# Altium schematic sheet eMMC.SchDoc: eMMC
size A4; CompanyName: STMicroelectronics; DocumentNumber: MB1263; Revision: C-04; SheetNumber: 9; SheetTotal: 11; Project: STM32MP157-EVAL
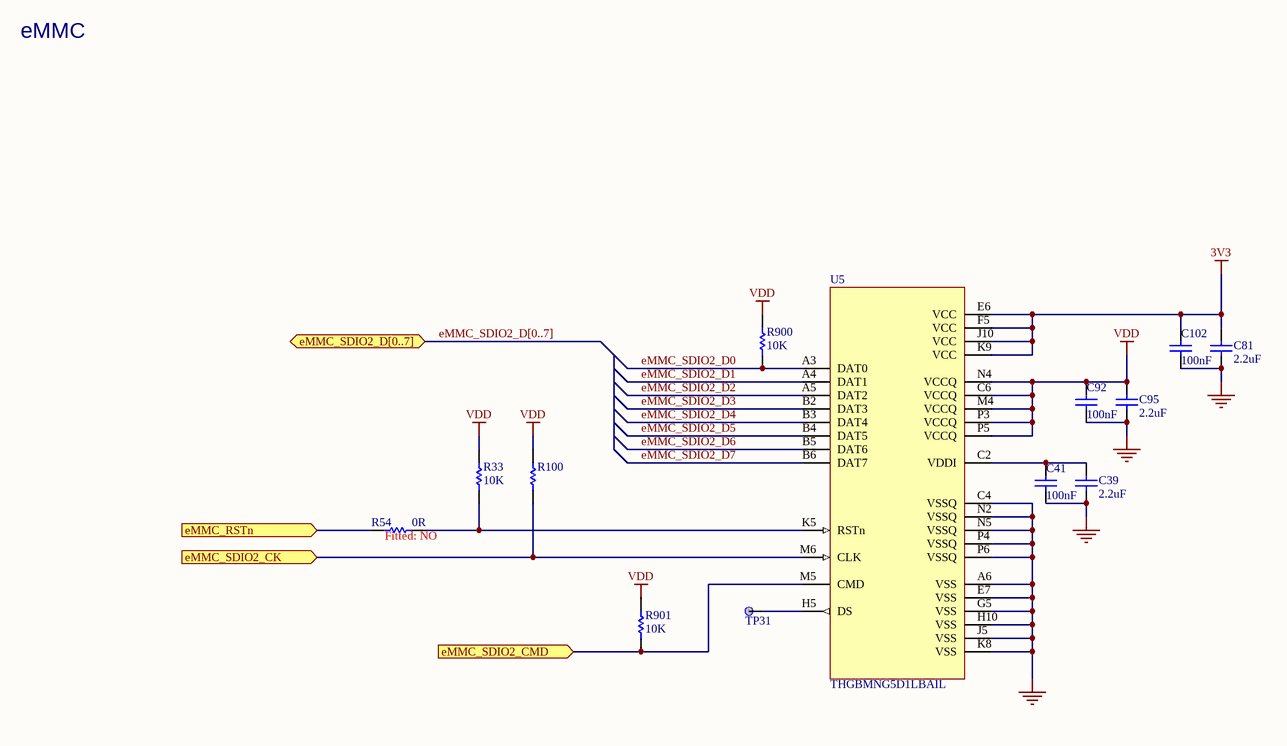
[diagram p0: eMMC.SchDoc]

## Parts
C39  2.2uF  [C0603]
C41  100nF  [C0402]
C81  2.2uF  [C0603]
C92  100nF  [C0402]
C95  2.2uF  [C0603]
C102  100nF  [C0402]
R33  10K  [R0402]
R54  0R  Fitted: NO  [R0402]
R100  10K  [R0402]  (value not drawn)
R900  10K  [R0402]
R901  10K  [R0402]
TP31  TP  [TP_SMD_1MM]  (value not drawn)  (no BOM)
U5  THGBMNG5D1LBAIL  [ICC_P-WFBGA153_13X11P5_P050]

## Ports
eMMC_RSTn (in), eMMC_SDIO2_CK (in), eMMC_SDIO2_CMD (in), eMMC_SDIO2_D[0..7] (bidir)

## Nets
3V3: C81.1 C102.2 U5.E6(VCC) U5.F5(VCC) U5.J10(VCC) U5.K9(VCC)
GND: C39.2 C41.1 C81.2 C92.1 C95.2 C102.1 U5.A6(VSS) U5.C4(VSSQ) U5.E7(VSS) U5.G5(VSS) U5.H10(VSS) U5.J5(VSS) U5.K8(VSS) U5.N2(VSSQ) U5.N5(VSSQ) U5.P4(VSSQ) U5.P6(VSSQ)
VDD: C92.2 C95.1 R33.2 R100.2 R900.2 R901.2 U5.C6(VCCQ) U5.M4(VCCQ) U5.N4(VCCQ) U5.P3(VCCQ) U5.P5(VCCQ)
eMMC_RSTn: R54.1 ; port eMMC_RSTn
eMMC_SDIO2_CK: R100.1 U5.M6(CLK) ; port eMMC_SDIO2_CK
eMMC_SDIO2_CMD: R901.1 U5.M5(CMD) ; port eMMC_SDIO2_CMD
eMMC_SDIO2_D0: R900.1 U5.A3(DAT0)
eMMC_SDIO2_D1: U5.A4(DAT1)
eMMC_SDIO2_D2: U5.A5(DAT2)
eMMC_SDIO2_D3: U5.B2(DAT3)
eMMC_SDIO2_D4: U5.B3(DAT4)
eMMC_SDIO2_D5: U5.B4(DAT5)
eMMC_SDIO2_D6: U5.B5(DAT6)
eMMC_SDIO2_D7: U5.B6(DAT7)
NetC39_1: C39.1 C41.2 U5.C2(VDDI)
NetR33_1: R33.1 R54.2 U5.K5(RSTn)
NetTP31_1: TP31.1 U5.H5(DS)

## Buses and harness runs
bus eMMC_SDIO2_D[0..7] = port eMMC_SDIO2_D[0..7]

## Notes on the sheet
- eMMC

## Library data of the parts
C39 C81 C95 = Cap_2.2uF_X5R_10%_0603: Capacitor,2.2uF,10V, X5R,10%,0603,YAGEO; Manuf_Part_1: CC0603KRX5R6BB225; Manuf_Part_2: C0603C225K8PACTU; Manuf_2: KEMET; Fitted: YES; Ordered_By: Subcon
C41 C92 C102 = Cap_100nF_X7R_10%_0402: Capacitor,100nF,16V,X7R,10%,0402,YAGEO; Manuf_Part_1: CC0402KRX7R7BB104; Fitted: YES; Ordered_By: Subcon
R33 R100 R900 R901 = Res_10K_1%_0402: Resistor,10K,0402,1%,YAGEO; Manuf_Part_1: RC0402FR-0710KL; Order_Code: 9239359RL; Fitted: YES; Ordered_By: Subcon
R54 = Res_0_5%_0402: Resistor,0R,0402,5%,YAGEO; Manuf_Part_1: RC0402JR-070RL; Order_Code: 2363467; Ordered_By: Subcon
TP31 = TP 1mm: Test Point; Fitted: YES
U5 = eMMC_THGBMNG5D1LBAIL: eMMC 4GB 153 Balls WFBGA 15nm; Manuf_1: KIOXIA; Manuf_Part_1: THGBMTG5D1LBAIL; ECCN_US/EU: EAR99; Fitted: YES; Ordered_By: Subcon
